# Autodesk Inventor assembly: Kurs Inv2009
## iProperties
Shininess: 64.0
Length Units: 11269
Angle Units: 11279
Time Units: 11290
Mass Units: 11283
Length Display Precision: 3
Angle Display Precision: 2
Compacted: True
Part Number: Kurs Inv2009
Document SubType Name: Assembly
Created: 2003-08
Designer: JWe
Manufacturer: Standard
Standards Organization: Custom
Density: 0.0
Volumn: 0.0
Area: 0.0
PropertySet Name: Model Information
Control State: 0
Master: False
Checked Out: False
Author: Administratör
